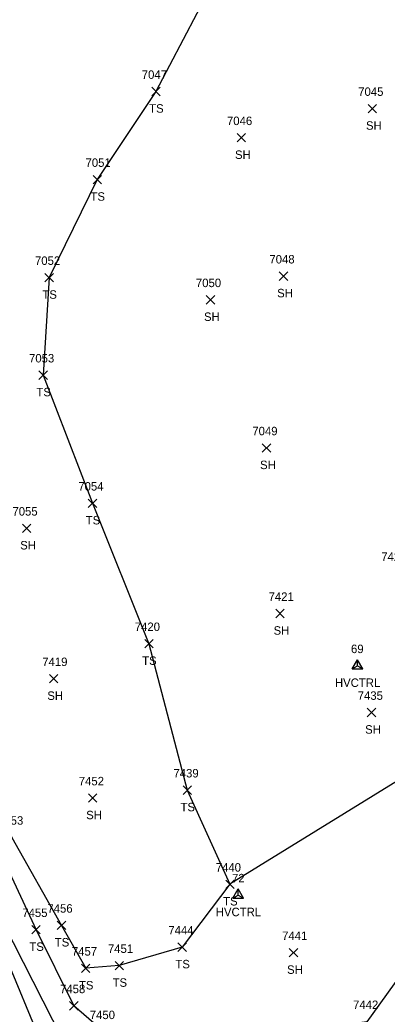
# Model space of a CAD drawing. Extents: x 1472233 to 1475777, y 540726 to 543442.
# Drawn here: x 1472796.2 to 1472882.9, y 541014 to 541249 of the extents above; entities that cross this region are included whole.
import ezdxf

# ---------------------------------------------------------------- set-up
doc = ezdxf.new("R2010")
doc.units = 0
for name, color, linetype in [('C_A', 7, 'Continuous'), ('C_I', 7, 'Continuous'), ('CPSM', 7, 'Continuous'), ('L_A', 7, 'Continuous'), ('L_I', 7, 'Continuous'), ('L_TIC', 7, 'Continuous'), ('LABL', 7, 'Continuous'), ('LELB', 7, 'Continuous'), ('PET', 7, 'Continuous')]:
    doc.layers.add(name, color=color, linetype=linetype)

msp = doc.modelspace()

# ---------------------------------------------------------------- linework, layer by layer
at = {"layer": 'CPSM'}
for p, q in [((1472874.62, 541095.59), (1472875.87, 541097.76)), ((1472877.12, 541095.59), (1472875.87, 541097.76)), ((1472875.87, 541096.31), (1472875.87, 541097.76)), ((1472874.62, 541095.59), (1472875.87, 541096.31)), ((1472874.62, 541095.59), (1472877.12, 541095.59)), ((1472875.87, 541096.31), (1472875.87, 541096.31)), ((1472875.87, 541096.31), (1472877.12, 541095.59)), ((1472846.48, 541041.41), (1472847.73, 541043.57)), ((1472848.98, 541041.41), (1472847.73, 541043.57)), ((1472847.73, 541042.13), (1472847.73, 541043.57)), ((1472846.48, 541041.41), (1472847.73, 541042.13)), ((1472846.48, 541041.41), (1472848.98, 541041.41)), ((1472847.73, 541042.13), (1472847.73, 541042.13)), ((1472847.73, 541042.13), (1472848.98, 541041.41))]:
    msp.add_line(p, q, dxfattribs=at)
at = {"layer": 'L_TIC'}
for points in [[(1472827.3, 541231.05), (1472829.3, 541233.05)], [(1472829.3, 541231.05), (1472827.3, 541233.05)], [(1472878.4, 541227.02), (1472880.4, 541229.02)], [(1472880.4, 541227.02), (1472878.4, 541229.02)], [(1472847.48, 541220.12), (1472849.48, 541222.12)], [(1472849.48, 541220.12), (1472847.48, 541222.12)], [(1472813.45, 541210.24), (1472815.45, 541212.24)], [(1472815.45, 541210.24), (1472813.45, 541212.24)], [(1472802.09, 541187.07), (1472804.09, 541189.07)], [(1472804.09, 541187.07), (1472802.09, 541189.07)], [(1472857.43, 541187.41), (1472859.43, 541189.41)], [(1472859.43, 541187.41), (1472857.43, 541189.41)], [(1472840.17, 541181.82), (1472842.17, 541183.82)], [(1472842.17, 541181.82), (1472840.17, 541183.82)], [(1472800.69, 541164.01), (1472802.69, 541166.01)], [(1472802.69, 541164.01), (1472800.69, 541166.01)], [(1472853.4, 541146.8), (1472855.4, 541148.8)], [(1472855.4, 541146.8), (1472853.4, 541148.8)], [(1472812.32, 541133.73), (1472814.32, 541135.73)], [(1472814.32, 541133.73), (1472812.32, 541135.73)], [(1472796.77, 541127.81), (1472798.77, 541129.81)], [(1472798.77, 541127.81), (1472796.77, 541129.81)], [(1472856.59, 541107.66), (1472858.59, 541109.66)], [(1472858.59, 541107.66), (1472856.59, 541109.66)], [(1472825.65, 541100.53), (1472827.65, 541102.53)], [(1472827.65, 541100.53), (1472825.65, 541102.53)], [(1472803.17, 541092.25), (1472805.17, 541094.25)], [(1472805.17, 541092.25), (1472803.17, 541094.25)], [(1472878.2, 541084.27), (1472880.2, 541086.27)], [(1472880.2, 541084.27), (1472878.2, 541086.27)], [(1472834.7, 541065.92), (1472836.7, 541067.92)], [(1472836.7, 541065.92), (1472834.7, 541067.92)], [(1472812.35, 541064.05), (1472814.35, 541066.05)], [(1472814.35, 541064.05), (1472812.35, 541066.05)], [(1472844.77, 541043.66), (1472846.77, 541045.66)], [(1472846.77, 541043.66), (1472844.77, 541045.66)], [(1472844.77, 541043.66), (1472846.77, 541045.66)], [(1472846.77, 541043.66), (1472844.77, 541045.66)], [(1472799.01, 541032.93), (1472801.01, 541034.93)], [(1472801.01, 541032.93), (1472799.01, 541034.93)], [(1472805.01, 541033.96), (1472807.01, 541035.96)], [(1472807.01, 541033.96), (1472805.01, 541035.96)], [(1472833.49, 541028.8), (1472835.49, 541030.8)], [(1472835.49, 541028.8), (1472833.49, 541030.8)], [(1472859.78, 541027.5), (1472861.78, 541029.5)], [(1472861.78, 541027.5), (1472859.78, 541029.5)], [(1472810.72, 541023.81), (1472812.72, 541025.81)], [(1472812.72, 541023.81), (1472810.72, 541025.81)], [(1472810.72, 541023.81), (1472812.72, 541025.81)], [(1472812.72, 541023.81), (1472810.72, 541025.81)], [(1472818.66, 541024.44), (1472820.66, 541026.44)], [(1472820.66, 541024.44), (1472818.66, 541026.44)], [(1472807.93, 541014.93), (1472809.93, 541016.93)], [(1472809.93, 541014.93), (1472807.93, 541016.93)], [(1472807.93, 541014.93), (1472809.93, 541016.93)], [(1472809.93, 541014.93), (1472807.93, 541016.93)]]:
    msp.add_lwpolyline(points, dxfattribs=at)
at = {"layer": 'LABL'}
msp.add_lwpolyline([(1472934.66, 541070.89), (1472902.08, 541045.59), (1472878.1, 541012.18), (1472852.69, 540994.21), (1472843.58, 540991.62), (1472842.46, 540986.71), (1472841.95, 540981.25), (1472845.46, 540968.73), (1472844.31, 540955.79), (1472840.71, 540945.45), (1472841.17, 540943.94), (1472845.65, 540929.61), (1472856.73, 540903.16), (1472864.12, 540875.89)], dxfattribs=at)
at = {"layer": 'LELB'}
for points in [[(1472858.93, 541384.48), (1472882.55, 541329.13), (1472858.46, 541287.49), (1472841.15, 541256.75), (1472828.3, 541232.05), (1472814.45, 541211.24), (1472803.09, 541188.07), (1472801.69, 541165.01), (1472813.32, 541134.73), (1472826.65, 541101.53), (1472835.7, 541066.92), (1472845.77, 541044.66)], [(1472694.17, 541336.7), (1472710.29, 541363.82), (1472724.01, 541367.47), (1472732.84, 541358.02), (1472735.8, 541341.69), (1472737.45, 541336.78), (1472738.6, 541320.92), (1472714.32, 541313.69), (1472692.63, 541308.44), (1472692.61, 541304.72), (1472694.99, 541295.51), (1472702.18, 541269.11), (1472714.98, 541232.25), (1472725.57, 541201.65), (1472739.9, 541163.72), (1472759.74, 541112.63), (1472772.2, 541081.83), (1472792.33, 541035.43), (1472808.54, 541003.5), (1472813.85, 541002.68), (1472821.82, 541001.88), (1472830.88, 541001.11)], [(1472688.47, 541308.96), (1472690.49, 541295.21), (1472699.31, 541268.29), (1472714.98, 541232.25), (1472728.45, 541202.22), (1472744.08, 541165.57), (1472763.48, 541113.22), (1472778.05, 541082.98), (1472790.98, 541053.2), (1472800.01, 541033.93), (1472808.93, 541015.93)], [(1472701.54, 541300.28), (1472712.43, 541272.5), (1472721.13, 541235.34), (1472733.49, 541204), (1472751.82, 541168.92), (1472768.47, 541115.66), (1472782.99, 541084.8), (1472794.3, 541055.75), (1472806.01, 541034.96), (1472811.72, 541024.81)], [(1473012.54, 541139.74), (1472961.33, 541130.07), (1472924.01, 541106.97), (1472910.79, 541092.53), (1472886.38, 541069.74), (1472845.77, 541044.66), (1472834.49, 541029.8), (1472819.66, 541025.44), (1472811.72, 541024.81)], [(1472878.1, 541012.18), (1472847.07, 541007.93), (1472840.09, 541003.77), (1472825.52, 541006.05), (1472816.04, 541009.8), (1472808.93, 541015.93)]]:
    msp.add_lwpolyline(points, dxfattribs=at)
at = {"layer": 'PET'}
msp.add_lwpolyline([(1472697.31, 541267.54), (1472711.09, 541230.89), (1472722.86, 541201.14), (1472737.78, 541162.9), (1472758.04, 541112.1), (1472770.41, 541081.49), (1472789.89, 541034.49), (1472803.92, 541000.71), (1472824.34, 540950.14), (1472844.22, 540900.95), (1472854.97, 540872.19)], dxfattribs=at)

# ---------------------------------------------------------------- texts
at = {"layer": 'C_A'}
for p in [(1472870.56, 541091.31), (1472842.43, 541037.13)]:
    msp.add_text('HVCTRL', height=2, dxfattribs=at).set_placement(p)
at = {"layer": 'C_I'}
for s, p in [('69', (1472874.35, 541099.31)), ('72', (1472846.27, 541045.13))]:
    msp.add_text(s, height=2, dxfattribs=at).set_placement(p)
at = {"layer": 'L_A'}
for s, p in [('TS', (1472826.71, 541227.05)), ('SH', (1472877.89, 541223.02)), ('SH', (1472846.97, 541216.12)), ('TS', (1472812.86, 541206.24)), ('TS', (1472801.5, 541183.07)), ('SH', (1472856.92, 541183.41)), ('SH', (1472839.65, 541177.82)), ('TS', (1472800.1, 541160.01)), ('SH', (1472852.89, 541142.8)), ('TS', (1472811.73, 541129.73)), ('SH', (1472796.26, 541123.81)), ('SH', (1472856.08, 541103.66)), ('TS', (1472825.06, 541096.53)), ('SH', (1472802.66, 541088.25)), ('SH', (1472877.69, 541080.27)), ('TS', (1472834.11, 541061.92)), ('SH', (1472811.84, 541060.05)), ('TS', (1472844.18, 541039.66)), ('TS', (1472844.18, 541039.66)), ('TS', (1472804.42, 541029.96)), ('TS', (1472798.42, 541028.93)), ('TS', (1472832.9, 541024.8)), ('SH', (1472859.27, 541023.5)), ('TS', (1472818.07, 541020.44)), ('TS', (1472810.13, 541019.81)), ('TS', (1472810.13, 541019.81))]:
    msp.add_text(s, height=2, dxfattribs=at).set_placement(p)
at = {"layer": 'L_I'}
for s, p in [('7047', (1472824.96, 541235.05)), ('7045', (1472876.06, 541231.02)), ('7046', (1472845.08, 541224.12)), ('7051', (1472811.68, 541214.24)), ('7052', (1472799.75, 541191.07)), ('7048', (1472855.09, 541191.41)), ('7050', (1472837.74, 541185.82)), ('7053', (1472798.35, 541168.01)), ('7049', (1472851.06, 541150.8)), ('7054', (1472809.98, 541137.73)), ('7055', (1472794.43, 541131.81)), ('7422', (1472881.5, 541121.11)), ('7421', (1472854.9, 541111.66)), ('7420', (1472823.31, 541104.53)), ('7419', (1472801.47, 541096.25)), ('7435', (1472875.94, 541088.27)), ('7439', (1472832.44, 541069.92)), ('7452', (1472810.09, 541068.05)), ('7453', (1472791.04, 541058.75)), ('7440', (1472842.43, 541047.66)), ('7440', (1472842.43, 541047.66)), ('7455', (1472796.75, 541036.93)), ('7456', (1472802.69, 541037.96)), ('7444', (1472831.23, 541032.8)), ('7441', (1472858.09, 541031.5)), ('7457', (1472808.46, 541027.81)), ('7457', (1472808.46, 541027.81)), ('7451', (1472816.97, 541028.44)), ('7458', (1472805.67, 541018.93)), ('7458', (1472805.67, 541018.93)), ('7442', (1472874.84, 541015.18)), ('7442', (1472874.84, 541015.18)), ('7450', (1472812.69, 541012.8))]:
    msp.add_text(s, height=2, dxfattribs=at).set_placement(p)

doc.saveas('drawing.dxf')
